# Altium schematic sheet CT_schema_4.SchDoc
size 421 x 246 mm
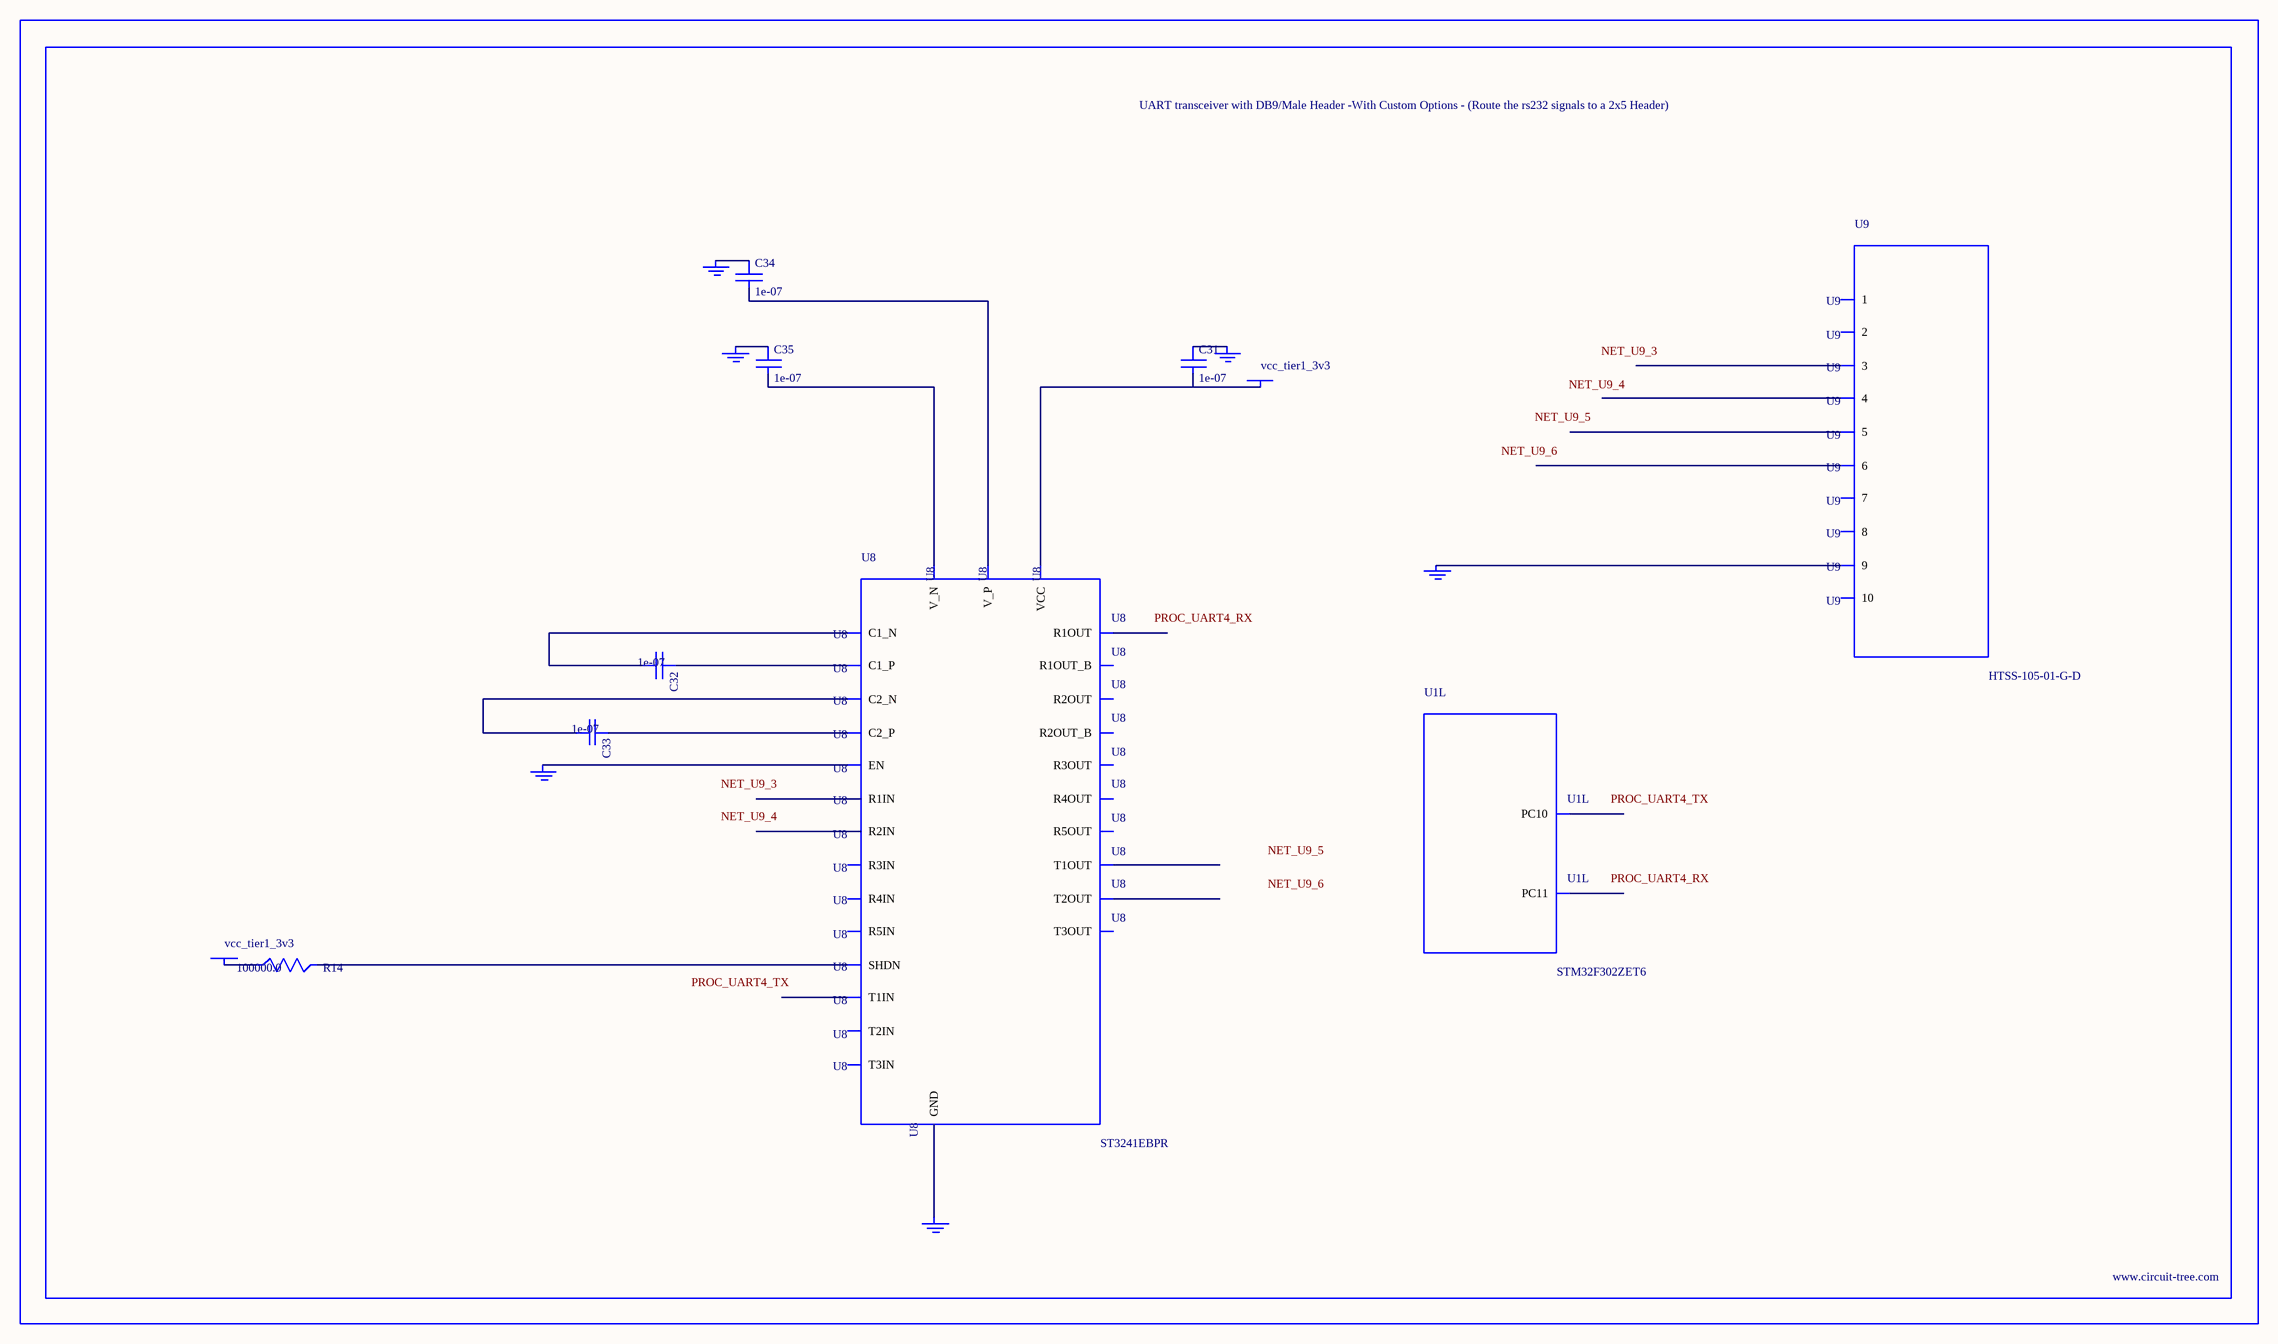
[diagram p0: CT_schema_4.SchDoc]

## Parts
BORDER3  (no value)
C31  1e-07  [C0402]
C32  1e-07  [C0402]
C33  1e-07  [C0402]
C34  1e-07  [C0402]
C35  1e-07  [C0402]
GND_INSTANCE_3_0  (no value)
GND_INSTANCE_3_1  (no value)
GND_INSTANCE_3_2  (no value)
GND_INSTANCE_3_3  (no value)
GND_INSTANCE_3_4  (no value)
GND_INSTANCE_3_5  (no value)
POWER_INSTANCE_3_0  vcc_tier1_3v3
POWER_INSTANCE_3_1  vcc_tier1_3v3
R14  100000.0  [R0603]
U1  STM32F302ZET6  [LQFP144]  (part L of 12)
U8  ST3241EBPR  [SSOP-28]
U9  HTSS-105-01-G-D  [HTSS-105-01-G-D]

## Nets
NetC31_1: C31.1 GND_INSTANCE_3_2.0(GND)
NetC31_2: C31.2 POWER_INSTANCE_3_1.0(PWR) U8.26(VCC)
NetC32_1: C32.1 U8.28(C1_P)
NetC32_2: C32.2 U8.24(C1_N)
NetC33_1: C33.1 U8.1(C2_P)
NetC33_2: C33.2 U8.2(C2_N)
NetC34_1: C34.1 GND_INSTANCE_3_3.0(GND)
NetC34_2: C34.2 U8.27(V_P)
NetC35_1: C35.1 GND_INSTANCE_3_0.0(GND)
NetC35_2: C35.2 U8.3(V_N)
NetGND_INSTANCE_3_1_0: GND_INSTANCE_3_1.0(GND) U8.23(EN)
NetGND_INSTANCE_3_4_0: GND_INSTANCE_3_4.0(GND) U8.25(GND)
NetGND_INSTANCE_3_5_0: GND_INSTANCE_3_5.0(GND) U9.9
NetPOWER_INSTANCE_3_0_0: POWER_INSTANCE_3_0.0(PWR) R14.1
NetR14_2: R14.2 U8.22(SHDN)

Not connected (* = marked no-connect by the designer): U1 111(PC10) 112(PC11); U8 4(R1IN) 5(R2IN) 6(R3IN) 7(R4IN) 8(R5IN) 9(T1OUT) 10(T2OUT) 11(T3OUT) 12(T3IN) 13(T2IN) 14(T1IN) 15(R5OUT) 16(R4OUT) 17(R3OUT) 18(R2OUT) 19(R1OUT) 20(R2OUT_B) 21(R1OUT_B); U9 1 2 3 4 5 6 7 8 10

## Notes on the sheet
- Labels drawn without touching a wire or pin: NET_U9_3, NET_U9_4, NET_U9_5, NET_U9_6, PROC_UART4_RX, PROC_UART4_TX

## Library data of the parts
BORDER3 = BORDER_PAGE3
C31-C35 = C0402C104K3RACTU
GND_INSTANCE_3_0-GND_INSTANCE_3_5 = GND
POWER_INSTANCE_3_0 POWER_INSTANCE_3_1 = PWR
R14 = RC0603JR-07100KL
